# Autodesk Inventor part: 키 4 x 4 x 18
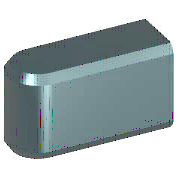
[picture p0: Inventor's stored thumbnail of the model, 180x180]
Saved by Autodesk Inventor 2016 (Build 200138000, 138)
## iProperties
IsCustomPart: 1
Created: 2012-02
Part Number: 키 4 x 4 x 18
Material: 강철, 연강
Description: 키 및 해당 키홈
Document SubType Name: Modeling
Standard: KS B 1311
Designer: mduedu
Standards Organization: KS
Language: ko-KR
Size Designation: 4 x 4 x 18
Categories: <MemberInstance><Categories><Category DisplayName="샤프트 부품" InternalName="7f7aeb1f-a693-4053-b835-cee3144e0d98" Mnemonic="SHFT"><Category DisplayName="키" Interna
Density: 1 g/cm^3
Appearance: 파란색 - 벽 페인트 - 광택
Author: mduedu
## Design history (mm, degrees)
sketch "스케치1"
  geometry: L1 (2, 2)-(18, 2); L2 (18, 2)-(18, -2); L3 (18, -2)-(2, -2); L4 (0, 7)-(0, -7) reference; L5 (-5, 0)-(30, 0) reference; A1 r 2 centre (2, 0) between (2, 2) and (2, -2)
  constraints: 6 end point, 3 tangent, 2 point on circle, 1 centre point, 1 horizontal, 1 parallel, 1 perpendicular, 1 point on line
  dimensions: "d0" = 2 radius of A1 (= 0.5 x PB); "d7" = 18 distance between parallel lines of L2 L4 (= NLG)
workplane "Work Plane1"
workplane "Work Plane2"
extrude "본체1" new body sketch "스케치1" taper "d3" = 0 deg; stored distance "d4" = 10
workaxis "Work Axis1"
workplane "Work Plane4"
body "Solid1"
chamfer "모따기1" distance "d8" = 0.25 (= PHH); stored, may be unused: second distance "d9" = 0.25 (= PHH), angle "d13" = 45 deg
other parameters: "d1" = -2.5 (= -PNT), "d2" = 1.5 (= PH - PNT), "NLG" = 18 [user parameter; used in 2 equation terms], "PB" = 4 [user parameter; used in 1 equation term], "PNT" = 2.5 [user parameter; used in 2 equation terms], "PH" = 4 [user parameter; used in 1 equation term], "PHH" = 0.25 [user parameter; used in 2 equation terms], "d10" = 0, "d16" = 0, "d17" = 0, "d18" = 0, "RR" = 0.08 [user parameter], "WDMAX" = 12 [user parameter], "PLB1" = 18 (= NLG) [user parameter], "PUEB" = 1.8 [user parameter]
